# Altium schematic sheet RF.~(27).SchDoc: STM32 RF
size A4; Date: Not used; ApprovedBy: Not used; CheckedBy: Not used; Author: Not used; CompanyName: STMicroelectronics; DrawnBy: Not used; Engineer: Not used; Organization: Not used; Address1: Not used; Address2: Not used; Address3: Not used; Address4: Not used; DocumentNumber: 5; Revision: Not used; SheetNumber: 5; SheetTotal: 5
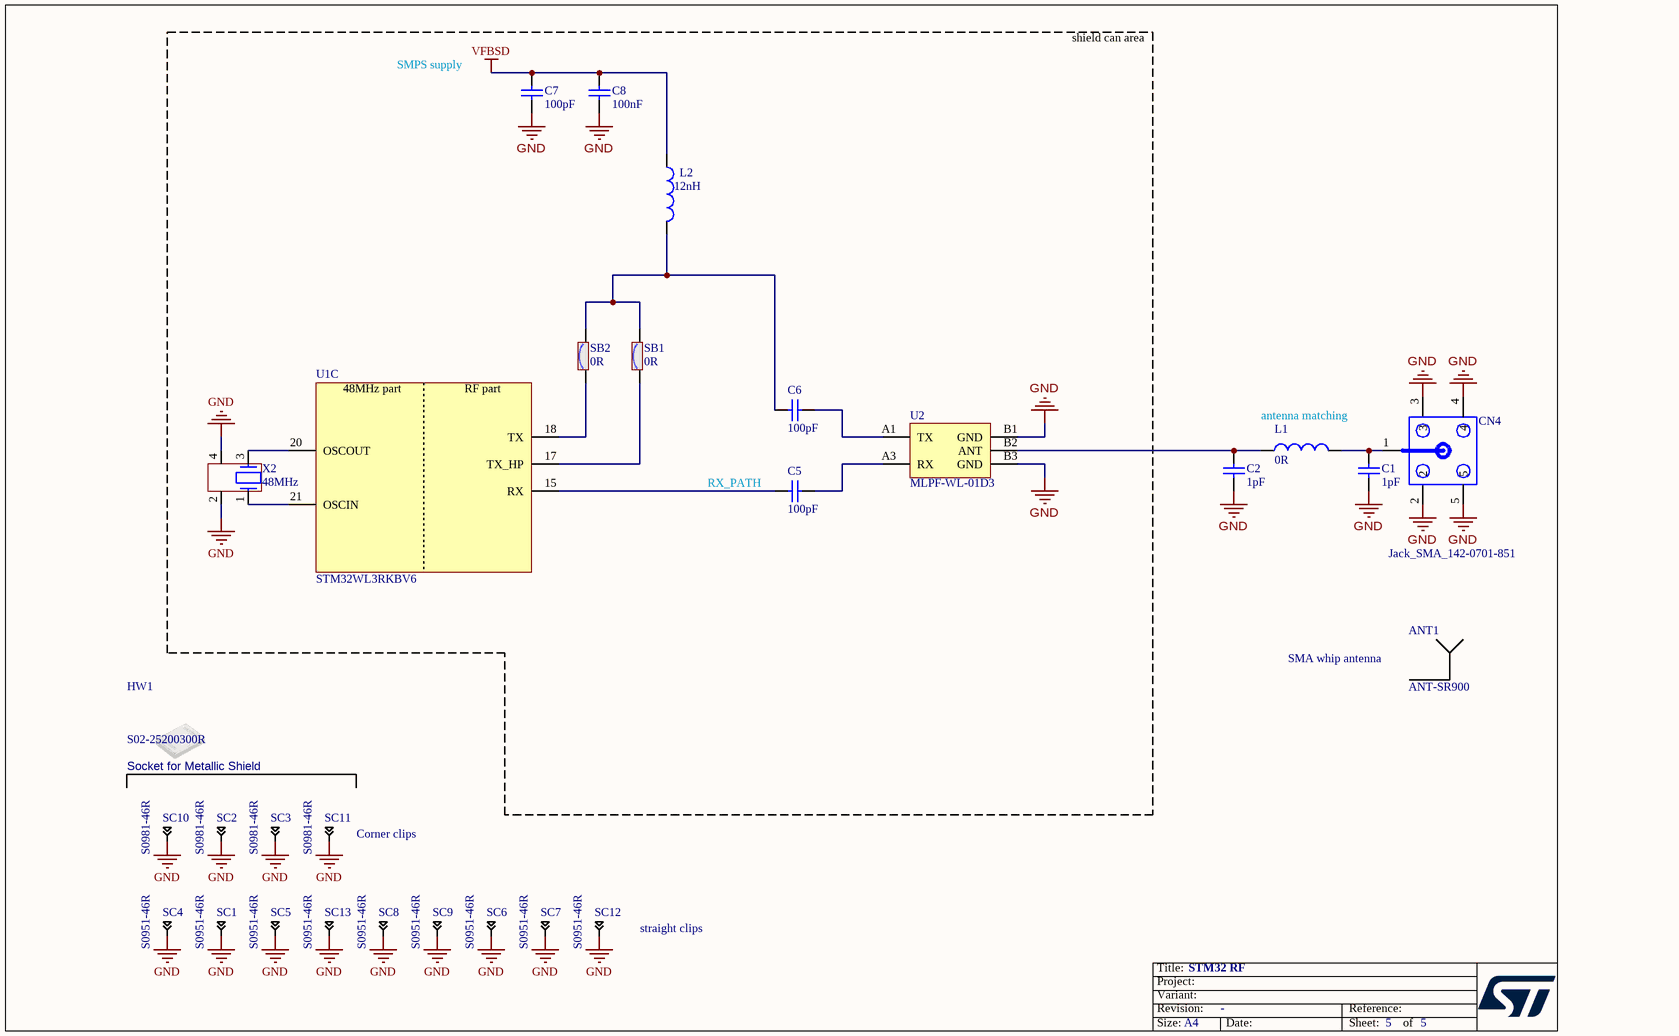
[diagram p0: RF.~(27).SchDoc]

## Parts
ANT1  value ANT-SR900  (hidden comment: ANT)
C1  value 1pF  [C0402]  (hidden comment: Capacitor)
C2  value 1pF  [C0402]  (hidden comment: Capacitor)
C5  value 100pF  [C0402]  (hidden comment: Capacitor)
C6  value 100pF  [C0402]  (hidden comment: Capacitor)
C7  value 100pF  [C0402]  (hidden comment: Capacitor)
C8  value 100nF  [C0402]  (hidden comment: Capacitor)
CN4  value Jack_SMA_142-0701-851  [CON_SMA-RF_CINCH_142-0701-851]  (hidden comment: mmcx)
HW1  value S02-25200300R  [SHIELD_HARWIN_S02-25200300_20X25_H3]  (hidden comment: S02-20150300)
L1  value 0R  [IND_0402_MURATA_LQW15AN_H0P5]  (hidden comment: Inductor)
L2  value 12nH  [IND_0402_MURATA_LQW15ANXXXX00_H0P5]  (hidden comment: Inductor)
SB1  value 0R  [SOLDER-BRIDGE_R0201_0R]  (hidden comment: SB_ON)
SB2  value 0R  [SOLDER-BRIDGE_R0201_0R]  (hidden comment: SB_ON)
SC1  value S0951-46R  [CLIP_HARWIN_S0951-46R]  (hidden comment: Shield-clip_S0951-46R)
SC2  value S0981-46R  [CLIP_HARWIN_S0981-46R]  (hidden comment: Shield-clip_S0951-46R)
SC3  value S0981-46R  [CLIP_HARWIN_S0981-46R]  (hidden comment: Shield-clip_S0951-46R)
SC4  value S0951-46R  [CLIP_HARWIN_S0951-46R]  (hidden comment: Shield-clip_S0951-46R)
SC5  value S0951-46R  [CLIP_HARWIN_S0951-46R]  (hidden comment: Shield-clip_S0951-46R)
SC6  value S0951-46R  [CLIP_HARWIN_S0951-46R]  (hidden comment: Shield-clip_S0951-46R)
SC7  value S0951-46R  [CLIP_HARWIN_S0951-46R]  (hidden comment: Shield-clip_S0951-46R)
SC8  value S0951-46R  [CLIP_HARWIN_S0951-46R]  (hidden comment: Shield-clip_S0951-46R)
SC9  value S0951-46R  [CLIP_HARWIN_S0951-46R]  (hidden comment: Shield-clip_S0951-46R)
SC10  value S0981-46R  [CLIP_HARWIN_S0981-46R]  (hidden comment: Shield-clip_S0951-46R)
SC11  value S0981-46R  [CLIP_HARWIN_S0981-46R]  (hidden comment: Shield-clip_S0951-46R)
SC12  value S0951-46R  [CLIP_HARWIN_S0951-46R]  (hidden comment: Shield-clip_S0951-46R)
SC13  value S0951-46R  [CLIP_HARWIN_S0951-46R]  (hidden comment: Shield-clip_S0951-46R)
U1  value STM32WL3RKBV6  [ICC_VFQFPN32-EPAD_5X5_P050]  (hidden comment: IC_STM32WL3R)  (part C of 3)
U2  value MLPF-WL-01D3  [ICC_CSPG5_1P5X1P9_P060]  (hidden comment: MLPF-WL-0xD3)
X2  value 48MHz  [CRY_NX1612SA_4P]  (hidden comment: XTAL_4_PINS)

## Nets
GND: C1.1 C2.1 C7.2 C8.1 CN4.2 CN4.3 CN4.4 CN4.5 SC1.1 SC2.1 SC3.1 SC4.1 SC5.1 SC6.1 SC7.1 SC8.1 SC9.1 SC10.1 SC11.1 SC12.1 SC13.1 U2.B1(GND) U2.B3(GND) X2.2 X2.4
VFBSD: C7.1 C8.2 L2.1
NetC1_2: C1.2 CN4.1 L1.2
NetC2_2: C2.2 L1.1 U2.B2(ANT)
NetC5_1: C5.1 U1.15(RX)
NetC5_2: C5.2 U2.A3(RX)
NetC6_1: C6.1 U2.A1(TX)
NetC6_2: C6.2 L2.2 SB1.2 SB2.2
NetSB1_1: SB1.1 U1.17(TX_HP)
NetSB2_1: SB2.1 U1.18(TX)
NetU1_20: U1.20(OSCOUT) X2.3
NetU1_21: U1.21(OSCIN) X2.1

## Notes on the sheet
- shield can area
- SMPS supply
- antenna matching
- (near C5) RX_PATH
- SMA whip antenna
- Socket for Metallic Shield
- (near SC11) Corner clips
- (near SC12) straight clips

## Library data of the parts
ANT1 = MCD-03598: Antenna, 868MHz To 915MHz, Compressed whip, SMA right angle; Part_Type: Misc; Part_Preference: Recommended; Manufacturer: LPRS; Component_Country_Of_Origin: China°; ShowFields: YES; ID: 5714
C1 C2 = MCD-01600: Capacitor, MLCC, 1pF, 50V, C0G/NP0, +/-0.1pF, 0402, T=0.5mm; Part_Preference: Recommended; Manufacturer: YAGEO; Manufacturer_Part_Number: CC0402BRNPO9BN1R0; Component_Country_Of_Origin: China; ShowFields: YES; ID: 3700
C5 = MCD-03446: Capacitor, MLCC, 100pF, 50V, C0G/NP0, +/-1%, 0402, T=0.5mm; Part_Preference: Recommended; Manufacturer: MURATA; Manufacturer_Part_Number: GCM1555C1H101FA16; Order_Code_RS: 247-7780; Component_Country_Of_Origin: China, Japan, Philippines, Singapore; ShowFields: YES; ID: 5562
C6 C7 = MCD-03446: Capacitor, MLCC, 100pF, 50V, C0G/NP0, +/-1%, 0402, T=0.5mm; Part_Preference: Recommended; Manufacturer: MURATA; Manufacturer_Part_Number: GCM1555C1H101FA16; Order_Code_RS: 247-7780; ShowFields: YES; ID: 5562; Component_Country_Of_Origin: China, Japan, Philippines, Singapore
C8 = MCD-03442: Capacitor, MLCC, 100nF, 25V, X7R, +/-10%, 0402, T=0.5mm; Part_Preference: Recommended; Manufacturer: MURATA; Manufacturer_Part_Number: GRM155R71E104KE14; Order_Code_RS: 247-8011; ShowFields: YES; ID: 5558; Component_Country_Of_Origin: China, Japan, Philippines, Singapore
CN4 = MCD-02072: Jack_SMA, VR, PCB edge, 50R, T=7.92mm; Part_Type: Connector; Part_Preference: Forbidden; Manufacturer: CINCH; Manufacturer_Part_Number: 142-0701-851; Order_Code_RS: 885-7532; Component_Country_Of_Origin: USA°°; ShowFields: YES; ID: 4172
HW1 = MCD-03503: RFI shield CAN, 25x20x3mm; Part_Type: Misc; Part_Preference: Recommended; Manufacturer: HARWIN; Order_Code_RS: 247-9197; Component_Country_Of_Origin: UK; ShowFields: YES; ID: 5619
L1 = MCD-01937: Resistor, 0R, 0402, +/-5%, 1/16W; Part_Preference: Recommended; Manufacturer: YAGEO; Manufacturer_Part_Number: RC0402JR-070RL; Order_Code_RS: 618-5804; Component_Country_Of_Origin: China; ShowFields: YES; ID: 4037
L2 = MCD-03456: Inductor, 12nH, +/-2%, 500mA, 0R14, 0402, T=0.5mm; Part_Preference: Recommended; Manufacturer: MURATA; Manufacturer_Part_Number: LQW15AN12NG00D; Order_Code_RS: 124-8172; ShowFields: YES; ID: 5572; Component_Country_Of_Origin: Japan, Malaysia
SB1 SB2 = MCD-03219: Solder Bridge ON, 0R, 0201, 1/20W; Part_Type: Misc; Part_Preference: Recommended; Manufacturer: YAGEO; Manufacturer_Part_Number: RC0201JR-070RL; Order_Code_RS: 198-7623; Component_Country_Of_Origin: China; ShowFields: YES; ID: 5335
SC1 SC4-SC9 SC12 SC13 = MCD-01587: RFI shield clip mini TIN SMD; Part_Type: Mechanical; Part_Preference: Recommended; Manufacturer: HARWIN; Component_Country_Of_Origin: Korea; ShowFields: YES; ID: 3687
SC2 SC3 SC10 SC11 = MCD-02164: Shield clip Harwin S0981-46R to fix RF shielded cavity; Part_Type: Mechanical; Part_Preference: Recommended; Order_Code_RS: 161-3702; Component_Country_Of_Origin: Korea; ShowFields: YES; ID: 4264
U1 = MCD-04431: MCU, ARM Cortex-M0 32-bit, 128KB Flash, 16KB SRAM, With Crypto; Part_Type: IC; Part_Preference: Recommended; Manufacturer: STMICROELECTRONICS; ShowFields: YES; ID: 6547; Component_Country_Of_Origin: Unknown
U2 = MCD-03962: IC, 862 To 928MHz,16dBm, 4L PCB, IPD for STM32WL3; Part_Preference: Recommended; Manufacturer: STMICROELECTRONICS; ShowFields: YES; ID: 6078; Component_Country_Of_Origin: Unknown
X2 = MCD-03559: Crystal, 48MHz, 8pF, +/-10ppm, 80R, 1.6x1.2mm; Part_Type: Crystal_Osc; Part_Preference: Recommended; Manufacturer: NDK; Manufacturer_Part_Number: NX1612SA-48.000MHz-EXS00A-CS12140; ShowFields: YES; ID: 5675; Component_Country_Of_Origin: Japan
